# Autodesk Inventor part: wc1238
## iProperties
Shininess: 64.0
Length Units: 11272
Angle Units: 11279
Time Units: 11290
Mass Units: 11286
Length Display Precision: 3
Angle Display Precision: 2
Compacted: True
Part Number: wc1238
Document SubType Name: Modeling
Created: 2004-08
Designer: John Blackburn
Manufacturer: Standard
Standards Organization: Custom
Density: 0.0
Volumn: 0.0
Area: 0.0
PropertySet Name: Model Information
Control State: 0
Master: False
Checked Out: False
Author: John Blackburn
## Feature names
1. Base1
